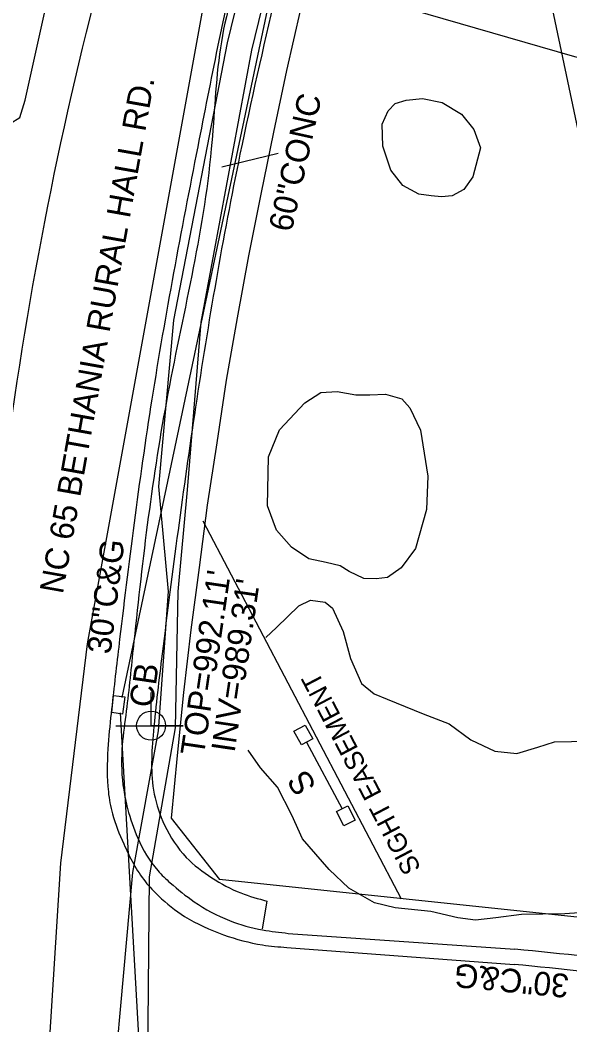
# Model space of a CAD drawing. Extents: x 1614611 to 1617571, y 898867 to 905462.
# Drawn here: x 1616026.4 to 1616119.3, y 904789.2 to 904959 of the extents above; entities that cross this region are included whole.
import ezdxf

# ---------------------------------------------------------------- set-up
doc = ezdxf.new("R2010")
doc.units = 0
for name, color, linetype in [('Exist Boundary Watershed Residential C 05', 7, 'Continuous'), ('Exist Building', 7, 'Continuous'), ('Exist Other Culture Sign', 7, 'Continuous'), ('Exist Other Culture Sign Text', 7, 'Continuous'), ('Exist Right of Way Easement Line Text', 7, 'Continuous'), ('Exist Roads Curbs Text', 7, 'Continuous'), ('Exist Roads EOP Other Leader', 7, 'Continuous'), ('Exist Roads EOP Other Text', 7, 'Continuous'), ('Exist Roads EOP Text', 7, 'Continuous'), ('Exist Structure Minor Catch Basin Top Elevation', 7, 'Continuous'), ('Exist Structure Minor Pipes RCP 15 Inch Invert', 7, 'Continuous'), ('Exist Utilities Power Joint Use Telephone CELL', 7, 'Continuous'), ('Exist Utilities Telephone UG Cable SUE LOS B', 7, 'Continuous'), ('Exist Utilities Telephone UG FO SUE LOS B', 7, 'Continuous'), ('Exist Utilities Water UG Line SUE LOS B', 7, 'Continuous'), ('Exist Vegetation Hedge Row', 7, 'Continuous'), ('Prop Drainage Structure Catch Basin Grate 840 03E Label', 7, 'Continuous'), ('Prop Drainage Structure Catch Basin Open Throat 4 CELL', 7, 'Continuous'), ('Prop Earthen Structure Cut Ditch Special Back of Curb Detail CELL', 7, 'Continuous'), ('Prop Earthen Structure Head Ditch Label', 7, 'Continuous'), ('Prop Easement Permanent Drainage', 7, 'Continuous'), ('Prop Plan Preparation Table Ditch Data CELL', 7, 'Continuous'), ('Raster_Level_2', 7, 'Continuous'), ('Scratch_Level_1', 7, 'Continuous'), ('Scratch_Level_9', 7, 'Continuous')]:
    doc.layers.add(name, color=color, linetype=linetype)

msp = doc.modelspace()

# ---------------------------------------------------------------- linework, layer by layer
at = {"layer": 'Exist Boundary Watershed Residential C 05'}
msp.add_line((1616071.71, 904804.64), (1616109.96, 904801.94), dxfattribs=at)
msp.add_ellipse((1616048.53, 904184.43), major_axis=(-608.22, -151.1), ratio=0.988965, start_param=4.29574, end_param=4.373231, dxfattribs=at)
msp.add_spline([(1616068.63, 904971.87), (1616066.73, 904971.82), (1616065.77, 904970.7), (1616058.7, 904937.22), (1616051.12, 904894.55), (1616045.49, 904852.68), (1616044.25, 904841.5), (1616043.61, 904835.73), (1616043.9, 904828.87), (1616044.56, 904825.73), (1616046.29, 904820.71), (1616049.67, 904815.24), (1616051.77, 904813.18), (1616055.82, 904809.98), (1616061.77, 904806.81), (1616067.37, 904805.22), (1616071.71, 904804.64)], degree=3, dxfattribs=at)
at = {"layer": 'Exist Building'}
for points in [[(1616073.92, 904836.49), (1616072.66, 904838.81), (1616074.57, 904839.85), (1616075.83, 904837.53)], [(1616081.74, 904826.21), (1616082.98, 904823.76), (1616081.08, 904822.8), (1616079.84, 904825.25)]]:
    msp.add_lwpolyline(points, close=True, dxfattribs=at)
at = {"layer": 'Exist Other Culture Sign'}
msp.add_line((1616074.8, 904836.97), (1616080.78, 904825.71), dxfattribs=at)
at = {"layer": 'Exist Roads EOP Other Leader'}
msp.add_line((1616060.5, 904934.18), (1616069.99, 904936.49), dxfattribs=at)
at = {"layer": 'Exist Utilities Power Joint Use Telephone CELL'}
msp.add_line((1616048.53, 904839.73), (1616048.53, 904839.73), dxfattribs=at)
msp.add_lwpolyline([(1616042.6, 904839.73), (1616053.93, 904839.7), (1616048.53, 904839.71), (1616048.53, 904845.36)], dxfattribs=at)
msp.add_circle((1616048.53, 904839.74), 2.45, dxfattribs=at)
at = {"layer": 'Exist Utilities Telephone UG Cable SUE LOS B'}
msp.add_lwpolyline([(1616000.59, 904958.72), (1616007.72, 904955.73), (1616012.67, 904953.3), (1616014.46, 904950.79), (1616016.39, 904946.13), (1616019.85, 904942.35), (1616024.71, 904941.54), (1616026.38, 904942.55), (1616027.24, 904945.45), (1616036.99, 904989.37), (1616051.33, 905054.35), (1616059.9, 905091.39), (1616063.65, 905103.92)], dxfattribs=at)
at = {"layer": 'Exist Utilities Telephone UG FO SUE LOS B'}
for points in [[(1616059.87, 904500.59), (1616050.65, 904559.97), (1616045.89, 904607.9), (1616045.92, 904641.06), (1616046.13, 904665.79), (1616046.08, 904684.35), (1616045.95, 904702.63), (1616046.43, 904719.24), (1616048.59, 904741.9), (1616047.87, 904770.66), (1616048.26, 904814.21), (1616052.64, 904839.37), (1616053.12, 904862.4), (1616054.68, 904879.58), (1616056.99, 904907.96), (1616065.53, 904953.89), (1616075.57, 904995.03), (1616088.33, 905050.27), (1616101.66, 905101.05), (1616103.63, 905109.27)], [(1616056.71, 904499.76), (1616046.9, 904559.71), (1616040.02, 904608.14), (1616037.39, 904639.63), (1616037.34, 904667.91), (1616042.38, 904684.44), (1616043.27, 904708.95), (1616043.41, 904719.76), (1616041.91, 904740.07), (1616040.77, 904762.99), (1616045.46, 904814.92), (1616049.8, 904838.86), (1616051.46, 904862.42), (1616049.82, 904880.18), (1616052.35, 904908.26), (1616061.41, 904955.15), (1616071.43, 904996.22), (1616084.1, 905051.84), (1616094.7, 905103.85), (1616096.08, 905109.05)]]:
    msp.add_lwpolyline(points, dxfattribs=at)
at = {"layer": 'Exist Utilities Water UG Line SUE LOS B'}
msp.add_lwpolyline([(1616045.84, 904527.76), (1616030.28, 904669.9), (1616029.26, 904727.11), (1616030.38, 904770.03), (1616033.26, 904816.5), (1616037.8, 904853.55), (1616057.25, 904960.81), (1616084.24, 905065.26), (1616095.12, 905109.27)], dxfattribs=at)
at = {"layer": 'Exist Vegetation Hedge Row'}
for points in [[(1616104.17, 904937.43), (1616102.89, 904932.5), (1616101.33, 904930.37), (1616099.38, 904929.31), (1616097.56, 904929.15), (1616095.84, 904929.27), (1616093.77, 904929.6), (1616091.05, 904931.06), (1616089.02, 904933.63), (1616087.68, 904937.67), (1616087.58, 904941.4), (1616088.55, 904943.67), (1616089.77, 904944.89), (1616091.59, 904945.46), (1616094.36, 904945.72), (1616097.7, 904945.05), (1616100.97, 904943.09), (1616103.04, 904940.53), (1616104.17, 904937.43)], [(1616095.03, 904876.27), (1616093.18, 904869.67), (1616090.79, 904866.42), (1616088.48, 904864.8), (1616086.57, 904864.54), (1616084.45, 904864.6), (1616081.97, 904865.8), (1616080.44, 904866.73), (1616078.08, 904867.34), (1616075.18, 904867.94), (1616072.27, 904869.89), (1616069.73, 904872.77), (1616068.22, 904876.87), (1616068.38, 904885.16), (1616070.23, 904889.73), (1616074.49, 904894.28), (1616077.18, 904896.04), (1616079.98, 904896.23), (1616083.09, 904895.63), (1616085.46, 904895.64), (1616088.12, 904895.78), (1616090.88, 904894.96), (1616092.24, 904893.46), (1616094.05, 904889.69), (1616095.25, 904881.93), (1616095.03, 904876.27)], [(1616067.92, 904854.62), (1616069.72, 904856.32), (1616073.46, 904860), (1616075.46, 904860.95), (1616077.94, 904860.62), (1616079.18, 904859.61), (1616080.98, 904855.64), (1616082.2, 904851.1), (1616084.08, 904846.88), (1616086.2, 904845.12), (1616088.41, 904844.23), (1616094.47, 904841.74)], [(1616094.47, 904841.74), (1616098.85, 904840.05), (1616102.53, 904837.34), (1616106.59, 904835.45), (1616110.29, 904835.02), (1616113.84, 904836.1), (1616116.69, 904837.02), (1616122.39, 904837.13)], [(1616122.48, 904808.19), (1616118.43, 904807.96), (1616114.67, 904807.88), (1616111.09, 904807.84), (1616106.74, 904807.27), (1616103.31, 904806.87), (1616100.35, 904807.26), (1616095.8, 904808.35), (1616089.77, 904808.93), (1616086.28, 904809.78), (1616081.95, 904812.25), (1616078.62, 904815.43), (1616074.11, 904820.59), (1616072.33, 904824.63), (1616069.87, 904829.36), (1616067.01, 904832.61), (1616064.93, 904835.62)]]:
    msp.add_lwpolyline(points, dxfattribs=at)
at = {"layer": 'Prop Drainage Structure Catch Basin Grate 840 03E Label'}
msp.add_lwpolyline([(1616080.53, 904965.77), (1616089.79, 904961.57), (1616119.67, 904952.95), (1616169.03, 904939.66), (1616202.83, 904932.09), (1616224.1, 904927.52), (1616253.54, 904922.63)], dxfattribs=at)
at = {"layer": 'Prop Drainage Structure Catch Basin Open Throat 4 CELL'}
msp.add_lwpolyline([(1616043.72, 904841.68), (1616041.88, 904841.96), (1616042.19, 904844.83), (1616044.1, 904844.61), (1616043.72, 904841.68)], dxfattribs=at)
at = {"layer": 'Prop Earthen Structure Cut Ditch Special Back of Curb Detail CELL'}
msp.add_line((1616057.26, 904874.35), (1616090.76, 904810.49), dxfattribs=at)
at = {"layer": 'Prop Earthen Structure Head Ditch Label'}
for p, q in [((1616010.65, 905462.23), (1616993.32, 900797.76)), ((1616073.79, 904960.86), (1616071.42, 904950.45)), ((1616071.42, 904950.45), (1616069.18, 904940.04)), ((1616069.18, 904940.04), (1616067.07, 904929.56)), ((1616067.07, 904929.56), (1616064.96, 904919.14)), ((1616064.96, 904919.14), (1616063.09, 904908.66)), ((1616063.09, 904908.66), (1616061.23, 904898.12)), ((1616061.23, 904898.12), (1616059.61, 904887.57)), ((1616059.61, 904887.57), (1616058, 904877.03)), ((1616058, 904877.03), (1616056.63, 904866.48)), ((1616056.63, 904866.48), (1616055.27, 904855.93)), ((1616055.27, 904855.93), (1616054.03, 904845.32)), ((1616054.03, 904845.32), (1616052.91, 904834.71)), ((1616052.91, 904834.71), (1616051.92, 904824.09)), ((1616051.92, 904824.09), (1616060.11, 904813.72)), ((1616238.41, 904794.93), (1616060.11, 904813.72))]:
    msp.add_line(p, q, dxfattribs=at)
at = {"layer": 'Prop Plan Preparation Table Ditch Data CELL'}
for p, q in [((1616099.57, 905109.44), (1616043.61, 904844.49)), ((1616043.29, 904841.89), (1616056.83, 904603.55))]:
    msp.add_line(p, q, dxfattribs=at)
at = {"layer": 'Raster_Level_2'}
msp.add_arc((1616679.54, 904799.06), 661.11, 164.05, 179.21667, dxfattribs=at)
at = {"layer": 'Scratch_Level_1'}
msp.add_line((1616068.1, 904810.08), (1616067.29, 904805.39), dxfattribs=at)
msp.add_spline([(1616069.52, 904963.23), (1616063.54, 904936.31), (1616056.04, 904893.58), (1616050.4, 904851.86), (1616048.94, 904838.8), (1616049.05, 904828.19), (1616050.82, 904822.93), (1616054.48, 904817.48), (1616058.79, 904814.03), (1616063.69, 904811.47), (1616068.1, 904810.08)], degree=3, dxfattribs=at)
at = {"layer": 'Scratch_Level_9'}
msp.add_line((1616071.47, 904802.26), (1616109.83, 904799.38), dxfattribs=at)
msp.add_ellipse((1616045.82, 904162.99), major_axis=(-616.84, -186.32), ratio=0.991347, start_param=4.247013, end_param=4.321869, dxfattribs=at)
msp.add_spline([(1616069.5, 904996.25), (1616064.75, 904977.29), (1616063.37, 904971.31), (1616056.4, 904937.58), (1616048.66, 904894.94), (1616043.06, 904853.03), (1616041.78, 904841.81), (1616041.23, 904835.81), (1616041.31, 904828.56), (1616041.99, 904824.85), (1616043.91, 904819.74), (1616047.58, 904813.35), (1616049.8, 904810.96), (1616054.2, 904807.49), (1616060.77, 904804.41), (1616067.34, 904802.68), (1616071.47, 904802.26)], degree=3, dxfattribs=at)

# ---------------------------------------------------------------- texts
at = {"layer": 'Exist Other Culture Sign Text'}
msp.add_text('S', height=4, rotation=121.3733, dxfattribs=at).set_placement((1616076.57, 904829.53))
at = {"layer": 'Exist Right of Way Easement Line Text'}
msp.add_text('SIGHT EASEMENT', height=3.2, rotation=117.6763, dxfattribs=at).set_placement((1616094.19, 904815.62))
at = {"layer": 'Exist Roads Curbs Text'}
msp.add_text('30"C&G', height=4, rotation=82.9808, dxfattribs=at).set_placement((1616041.69, 904851.71))
at = {"layer": 'Exist Roads EOP Other Text'}
msp.add_text('60"CONC', height=4, rotation=77.4622, dxfattribs=at).set_placement((1616072.25, 904923.02))
at = {"layer": 'Exist Roads EOP Text'}
for s, rotation, p in [('NC 65 BETHANIA RURAL HALL RD.', 79.9045, (1616033.62, 904861.87)), ('30"C&G', 174.4688, (1616119.25, 904797.69))]:
    msp.add_text(s, height=4, rotation=rotation, dxfattribs=at).set_placement(p)
at = {"layer": 'Exist Structure Minor Catch Basin Top Elevation'}
msp.add_text("TOP=992.11'", height=4, rotation=81.6333, dxfattribs=at).set_placement((1616057.43, 904834.5))
at = {"layer": 'Exist Structure Minor Pipes RCP 15 Inch Invert'}
msp.add_text("INV=989.31'", height=4, rotation=81.6333, dxfattribs=at).set_placement((1616062.63, 904835.09))
at = {"layer": 'Prop Easement Permanent Drainage'}
msp.add_text('CB', height=4, rotation=81.6333, dxfattribs=at).set_placement((1616048.77, 904842.65))

doc.saveas('drawing.dxf')
